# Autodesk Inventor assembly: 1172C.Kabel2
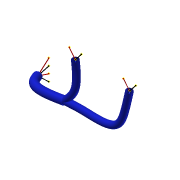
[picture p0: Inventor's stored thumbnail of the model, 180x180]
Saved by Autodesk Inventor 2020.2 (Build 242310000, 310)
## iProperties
Part Number: 1172C.Kabel2
Material: Ogólne
Description: 1172C
Part Number: 1172C.Kabel1
ParentFileIdentifier: 5|1|0|0|50|1|0|0|80|0|65|0|84|0|72|0|83|0|59|0|67|0|58|0|92|0|90|0|98|0|105|0|243|0|114|0|32|0|7|1|119|0|105|0|99|0|122|0|101|0|68|1|32|0|65|0|73|0|32|0|50|0|48
Part Number: 1172C.Kabel4
Part Number: 1172C.Kabel3
Manager: www.cadconsulting.pl
Company: Fabian Stasiak CAD Consulting
Created: 2014-09
Part Number: W_300_01.Wiązka przewodów1
Document SubType Name: Assembly
Designer: F.Stasiak
Catalog Web Link: www.expertbooks.pl
HarnessSettings: <HarnessSettings><Defaults><Segments><Diameter value="0.200 in" fromwires="True"/><Offset value="0.100 in"/><ColorStyle value="Niebieska - farba ścienna - lśnią
Author: F.Stasiak
Subject: Zbiór ćwiczeń. Autodesk Inventor 2020. Kurs Professional
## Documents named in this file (2)
- C:\2020_Kurs_Professional\R2 Wiązki\W_300_01\AIP\przewody i wiązki przewodów\W_300_01.Wiązka przewodów1.iam
- C:\2020_Kurs_Professional\R2 Wiązki\W_300_01\AIP\przewody i wiązki przewodów\W_300_01.Wiązka przewodów1.ipt
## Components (5 placed, 5 different names)
1. Wiązka przewodów1
2. HA_VC_179:1
3. HA_VC_184:1
4. HA_VC_189:1
5. HA_VC_194:1
